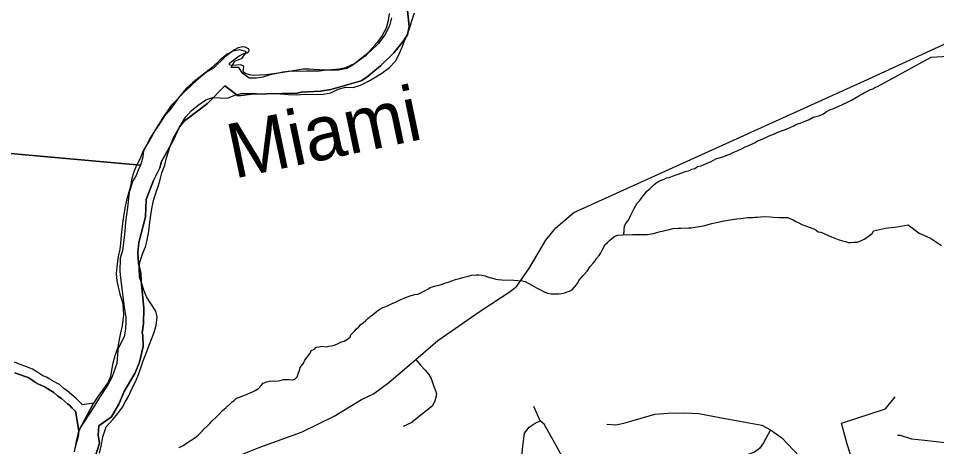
# Model space of a CAD drawing. Extents: x 0 to 34, y 0 to 22.
# Drawn here: x 3.323 to 4.119, y 17.214 to 17.586 of the extents above; entities that cross this region are included whole.
import ezdxf

# ---------------------------------------------------------------- set-up
doc = ezdxf.new("R2010")
doc.units = 0
for name, color, linetype in [('GM_X_Corporation', 7, 'Continuous'), ('GM_X_Major_River', 7, 'Continuous'), ('GM_X_Major_River_Text', 7, 'Continuous'), ('GM_X_Minor_River', 7, 'Continuous'), ('GM_X_Section', 7, 'Continuous'), ('GM_X_State_Route', 7, 'Continuous'), ('GM_X_Township_Road', 7, 'Continuous')]:
    doc.layers.add(name, color=color, linetype=linetype)

msp = doc.modelspace()

# ---------------------------------------------------------------- linework, layer by layer
at = {"layer": 'GM_X_Corporation'}
for points in [[(3.66027, 17.59244), (3.66153, 17.57843), (3.66011, 17.57121), (3.65674, 17.56596), (3.64838, 17.55552), (3.63677, 17.54452), (3.625, 17.53469), (3.62001, 17.53146), (3.59358, 17.52401), (3.58465, 17.52246), (3.56808, 17.52153), (3.56455, 17.52076), (3.52463, 17.5198), (3.51326, 17.51849), (3.50188, 17.52714), (3.48677, 17.51184), (3.46643, 17.49633), (3.46241, 17.49151), (3.45663, 17.47913), (3.44693, 17.46157), (3.44543, 17.45604), (3.4399, 17.44498), (3.43361, 17.42866), (3.43299, 17.41366), (3.42736, 17.39127), (3.42641, 17.38259), (3.42695, 17.37297), (3.42903, 17.36479), (3.42912, 17.35794), (3.43149, 17.33454), (3.4313, 17.321), (3.43021, 17.31263), (3.43079, 17.31107), (3.43091, 17.30105), (3.42783, 17.28746), (3.42393, 17.27842), (3.41461, 17.26212), (3.40987, 17.25112), (3.40354, 17.24031), (3.39245, 17.2323), (3.39208, 17.22427), (3.39303, 17.21741), (3.38732, 17.19913)], [(3.38732, 17.19913), (3.39303, 17.21741), (3.39208, 17.22427), (3.39245, 17.2323), (3.40354, 17.24031), (3.40987, 17.25112), (3.41461, 17.26212), (3.42393, 17.27842), (3.42783, 17.28746), (3.43091, 17.30105), (3.43079, 17.31107), (3.43021, 17.31263), (3.4313, 17.321), (3.43149, 17.33454), (3.42912, 17.35794), (3.42903, 17.36479), (3.42695, 17.37297), (3.42641, 17.38259), (3.42736, 17.39127), (3.43299, 17.41366), (3.43361, 17.42866), (3.4399, 17.44498), (3.44543, 17.45604), (3.44693, 17.46157), (3.45663, 17.47913), (3.46241, 17.49151), (3.46643, 17.49633), (3.48677, 17.51184), (3.50188, 17.52714), (3.51326, 17.51849), (3.52463, 17.5198), (3.56455, 17.52076), (3.56808, 17.52153), (3.58465, 17.52246), (3.59358, 17.52401), (3.62001, 17.53146), (3.625, 17.53469), (3.63677, 17.54452), (3.64838, 17.55552), (3.65674, 17.56596), (3.66011, 17.57121), (3.66153, 17.57843), (3.66027, 17.59244)]]:
    msp.add_lwpolyline(points, dxfattribs=at)
at = {"layer": 'GM_X_Major_River'}
msp.add_line((3.38806, 17.25203), (3.37508, 17.22818), dxfattribs=at)
for points in [[(3.64429, 17.58964), (3.64341, 17.58377), (3.64176, 17.57697), (3.63822, 17.57058), (3.63375, 17.5646), (3.62948, 17.55974), (3.62347, 17.55284), (3.61867, 17.54933), (3.61232, 17.54471), (3.60754, 17.54196), (3.60031, 17.54058), (3.5952, 17.5405), (3.59028, 17.5406), (3.58344, 17.53979), (3.57814, 17.53989), (3.57246, 17.53963), (3.56772, 17.53953), (3.56243, 17.53983), (3.55674, 17.53956), (3.55199, 17.5389), (3.54686, 17.53787), (3.54096, 17.53647), (3.53487, 17.53469), (3.52917, 17.53366), (3.52292, 17.53379), (3.51714, 17.53809), (3.51383, 17.5429), (3.50739, 17.54284), (3.51053, 17.54847), (3.51683, 17.55101), (3.52054, 17.55644), (3.51471, 17.55827), (3.50862, 17.55706), (3.50384, 17.5545), (3.49748, 17.54931), (3.49111, 17.54317), (3.48457, 17.53799), (3.47937, 17.53391), (3.47399, 17.52984), (3.46839, 17.52464), (3.46257, 17.51773), (3.45809, 17.51174), (3.45342, 17.50538), (3.44916, 17.50053), (3.44564, 17.49509), (3.44134, 17.48853), (3.43858, 17.48346), (3.43467, 17.47708), (3.43094, 17.4707), (3.42796, 17.46355), (3.42499, 17.45734), (3.42281, 17.45245), (3.42097, 17.44565), (3.4199, 17.43978), (3.41786, 17.43279), (3.41644, 17.42789), (3.41498, 17.42108), (3.41407, 17.41369), (3.413, 17.40782), (3.41252, 17.4029), (3.41204, 17.39759), (3.41132, 17.39039), (3.41065, 17.38546), (3.40939, 17.37922), (3.40826, 17.37032), (3.40758, 17.36445), (3.40821, 17.35817), (3.40923, 17.35283), (3.41081, 17.34653), (3.41294, 17.33965), (3.41377, 17.33393), (3.41386, 17.32862), (3.41338, 17.32388), (3.41271, 17.31895), (3.41126, 17.31291), (3.40999, 17.30591), (3.40911, 17.30022), (3.40651, 17.29306), (3.40467, 17.28664), (3.40342, 17.28078), (3.40255, 17.27529), (3.40056, 17.27039), (3.39606, 17.26365), (3.39236, 17.25859), (3.38806, 17.25203)], [(3.39306, 17.20882), (3.3945, 17.21487), (3.396, 17.22301), (3.39901, 17.23149), (3.40463, 17.23803), (3.4089, 17.24326), (3.41299, 17.24849), (3.41574, 17.25356), (3.41849, 17.25845), (3.42126, 17.26447), (3.42423, 17.27067), (3.42682, 17.27689), (3.42883, 17.28255), (3.43103, 17.28877), (3.43323, 17.29442), (3.43524, 17.30008), (3.43823, 17.30761), (3.44023, 17.3127), (3.44226, 17.31931), (3.44317, 17.32688), (3.44195, 17.33185), (3.43754, 17.33858), (3.43387, 17.34435), (3.43152, 17.34991), (3.4301, 17.35487), (3.42777, 17.36138), (3.42755, 17.36917), (3.42804, 17.37429), (3.43066, 17.38202), (3.43304, 17.38767), (3.43448, 17.39334), (3.43578, 17.4011), (3.4367, 17.40906), (3.43758, 17.41511), (3.43886, 17.42231), (3.44031, 17.42873), (3.44254, 17.43571), (3.44416, 17.44081), (3.44559, 17.44591), (3.44722, 17.45176), (3.44963, 17.45836), (3.45127, 17.46459), (3.4529, 17.47026), (3.45471, 17.47573), (3.4573, 17.48194), (3.46142, 17.48889), (3.46477, 17.49528), (3.4679, 17.50034), (3.47254, 17.50537), (3.4787, 17.51019), (3.48542, 17.5148), (3.49134, 17.51696), (3.49777, 17.51664), (3.5042, 17.51651), (3.5105, 17.51885), (3.51698, 17.52081), (3.52189, 17.52052), (3.52682, 17.52061), (3.53173, 17.52013), (3.53665, 17.52003), (3.54329, 17.52047), (3.5501, 17.52014), (3.5569, 17.51943), (3.56371, 17.51929), (3.57111, 17.51972), (3.58227, 17.51949), (3.58721, 17.51996), (3.59367, 17.52097), (3.60017, 17.52406), (3.60683, 17.52583), (3.61307, 17.5257), (3.61955, 17.52766), (3.62644, 17.53113), (3.63123, 17.53407), (3.63698, 17.53756), (3.64428, 17.54254), (3.6497, 17.54851), (3.65245, 17.55339), (3.65544, 17.56055), (3.65744, 17.56602), (3.66042, 17.5726), (3.66223, 17.57769), (3.66386, 17.58336), (3.66627, 17.59034)], [(3.37508, 17.22818), (3.3746, 17.22287), (3.37257, 17.21626), (3.37112, 17.21022)]]:
    msp.add_lwpolyline(points, dxfattribs=at)
at = {"layer": 'GM_X_Minor_River'}
msp.add_line((3.37508, 17.22818), (3.38806, 17.25203), dxfattribs=at)
for points in [[(4.06761, 17.52654), (4.11423, 17.55186), (4.19354, 17.55663)], [(3.84786, 17.39807), (3.84843, 17.40578), (3.84983, 17.40839), (3.85141, 17.41043), (3.8526, 17.4123), (3.85361, 17.41435), (3.85502, 17.41716), (3.85664, 17.42072), (3.85824, 17.42333), (3.85925, 17.42539), (3.86121, 17.42742), (3.86298, 17.42964), (3.86457, 17.43187), (3.86614, 17.43372), (3.86772, 17.43576), (3.87045, 17.43815), (3.87357, 17.4409), (3.87572, 17.44312), (3.87823, 17.44437), (3.88016, 17.44526), (3.88266, 17.44632), (3.88477, 17.44721), (3.88706, 17.44752), (3.88995, 17.44876), (3.89302, 17.44981), (3.89879, 17.4521), (3.9009, 17.4528), (3.90472, 17.45363), (3.90666, 17.45471), (3.90934, 17.45539), (3.91147, 17.45703), (3.91473, 17.45788), (3.918, 17.45911), (3.92012, 17.46019), (3.92339, 17.46161), (3.92763, 17.46376), (3.93243, 17.46532), (3.93588, 17.46654), (3.94088, 17.46829), (3.943, 17.46956), (3.94589, 17.47061), (3.95032, 17.47275), (3.95283, 17.47419), (3.9561, 17.47542), (3.96149, 17.47792), (3.96362, 17.47937), (3.96612, 17.48025), (3.96958, 17.48166), (3.97382, 17.48381), (3.97593, 17.48451), (3.97824, 17.48539), (3.98113, 17.48682), (3.98612, 17.48856), (3.98997, 17.48997), (3.99517, 17.49247), (3.99748, 17.49373), (4.00075, 17.49477), (4.00344, 17.49601), (4.00844, 17.49795), (4.01192, 17.49993), (4.01536, 17.50078), (4.01766, 17.50147), (4.02094, 17.50289), (4.02346, 17.50471), (4.02694, 17.50669), (4.02885, 17.5072), (4.03097, 17.50809), (4.03405, 17.50952), (4.03674, 17.51057), (4.04233, 17.51325), (4.04503, 17.51469), (4.04813, 17.51649), (4.0516, 17.51829), (4.05411, 17.51973), (4.05644, 17.52137), (4.05836, 17.52226), (4.06164, 17.52387), (4.06356, 17.52438), (4.06549, 17.52565), (4.06761, 17.52654)], [(3.64692, 17.33841), (3.64904, 17.3393), (3.65443, 17.34179), (3.65732, 17.34303), (3.65925, 17.34392), (3.66347, 17.3455), (3.66654, 17.34636), (3.66921, 17.34666), (3.67113, 17.34736), (3.6748, 17.34934), (3.67769, 17.35096), (3.67983, 17.35241), (3.68481, 17.35378), (3.68863, 17.35461), (3.69247, 17.35602), (3.69554, 17.35706), (3.69862, 17.35811), (3.70188, 17.35915), (3.70532, 17.35999), (3.7082, 17.36086), (3.71031, 17.36155), (3.7128, 17.36223), (3.71605, 17.36308), (3.71967, 17.36316), (3.72214, 17.36328), (3.72461, 17.36301), (3.72744, 17.36255), (3.73101, 17.36111), (3.73309, 17.36067), (3.73686, 17.3596), (3.73875, 17.35917), (3.74198, 17.35907), (3.75243, 17.35875), (3.75944, 17.35816), (3.76227, 17.3575), (3.76545, 17.3557), (3.76807, 17.35429), (3.772, 17.35189), (3.775, 17.35047), (3.77931, 17.34825), (3.78156, 17.34742), (3.78478, 17.34694), (3.78953, 17.3468), (3.79143, 17.34674), (3.79372, 17.34724), (3.79659, 17.34772), (3.7987, 17.34842), (3.80062, 17.34912), (3.80293, 17.35019), (3.8047, 17.35222), (3.80608, 17.35408), (3.80786, 17.35631), (3.80868, 17.35837), (3.81083, 17.36058), (3.81241, 17.36281), (3.81594, 17.3665), (3.81852, 17.37041), (3.82108, 17.37338), (3.82265, 17.37523), (3.82405, 17.37746), (3.8264, 17.38005), (3.82759, 17.38191), (3.8286, 17.38397), (3.82942, 17.38584), (3.83143, 17.38958), (3.83356, 17.39123), (3.83533, 17.39307), (3.83747, 17.3949), (3.8398, 17.39673), (3.84249, 17.39779), (3.84687, 17.39804), (3.84992, 17.39813), (3.85201, 17.39807), (3.85525, 17.39835), (3.86151, 17.39816), (3.86513, 17.39824), (3.86817, 17.39834), (3.87008, 17.39866), (3.87447, 17.39948), (3.87734, 17.40015), (3.88807, 17.40286), (3.89017, 17.40337), (3.89493, 17.4036), (3.89722, 17.40372), (3.90368, 17.40391), (3.90616, 17.40402), (3.91303, 17.40514), (3.91666, 17.40579), (3.92413, 17.40765), (3.92662, 17.40834), (3.93064, 17.40935), (3.93446, 17.41), (3.93656, 17.4105), (3.94152, 17.41111), (3.94344, 17.41162), (3.94572, 17.41174), (3.94897, 17.41221), (3.95107, 17.41253), (3.95507, 17.41298), (3.95697, 17.41292), (3.95944, 17.41304)], [(3.95944, 17.41304), (3.96135, 17.41317), (3.96363, 17.41329), (3.9663, 17.41359), (3.96916, 17.41369), (3.97447, 17.41353), (3.97713, 17.41326), (3.98225, 17.41291), (3.98453, 17.41284), (3.98776, 17.41293), (3.98985, 17.41287), (3.99173, 17.41205), (3.99454, 17.41083), (3.99679, 17.40943), (3.99942, 17.4084), (4.00203, 17.4068), (4.00523, 17.40576), (4.01238, 17.40307), (4.01444, 17.40206), (4.0163, 17.40067), (4.01819, 17.40024), (4.02007, 17.39961), (4.02439, 17.39777), (4.02777, 17.39634), (4.03078, 17.39511), (4.03359, 17.39388), (4.03736, 17.39263), (4.03982, 17.39217), (4.04245, 17.39133), (4.04454, 17.39127), (4.0474, 17.39156), (4.05007, 17.39167), (4.05237, 17.39236), (4.0543, 17.39344), (4.05623, 17.39433), (4.05854, 17.39559), (4.06087, 17.39723), (4.06321, 17.39944), (4.06434, 17.4015)], [(4.06434, 17.4015), (4.07447, 17.40361), (4.08474, 17.40475), (4.09425, 17.40647), (4.10376, 17.39943), (4.11365, 17.39505), (4.12316, 17.38858)], [(3.46222, 17.21356), (3.46569, 17.21536), (3.46841, 17.21736), (3.47576, 17.22208), (3.47868, 17.22446), (3.48201, 17.22777), (3.48397, 17.2298), (3.4865, 17.23201), (3.48866, 17.23441), (3.49082, 17.23662), (3.49395, 17.23976), (3.49667, 17.24214), (3.49963, 17.24566), (3.50255, 17.24804), (3.50802, 17.25319), (3.50995, 17.25427), (3.51191, 17.2563), (3.5146, 17.25736), (3.51671, 17.25824), (3.52113, 17.26001), (3.52364, 17.26107), (3.52575, 17.26196), (3.52806, 17.26303), (3.53097, 17.26484), (3.53332, 17.26742), (3.53489, 17.26927), (3.53817, 17.27069), (3.5418, 17.27153), (3.54502, 17.27125), (3.54826, 17.27153), (3.55075, 17.27202), (3.55266, 17.27253), (3.55571, 17.27263), (3.55761, 17.27257), (3.56026, 17.2723), (3.56256, 17.27299), (3.56451, 17.27483), (3.56576, 17.2784), (3.56658, 17.28047), (3.56722, 17.2831), (3.56999, 17.28682), (3.57101, 17.28926), (3.57416, 17.29315), (3.57555, 17.295), (3.57695, 17.29762), (3.57946, 17.29887), (3.58103, 17.30072), (3.5837, 17.30102), (3.5858, 17.30134), (3.58978, 17.30103), (3.59188, 17.30134), (3.59437, 17.30184), (3.59666, 17.30234), (3.59897, 17.30322), (3.60283, 17.30519), (3.60513, 17.30588), (3.60802, 17.3075), (3.61055, 17.30932), (3.61117, 17.3112), (3.61411, 17.31434), (3.61588, 17.31638), (3.61784, 17.31822), (3.61979, 17.32025), (3.62193, 17.32189), (3.62388, 17.32354), (3.62584, 17.32557), (3.62856, 17.32777), (3.63089, 17.3294), (3.63342, 17.33142), (3.63614, 17.33342), (3.63865, 17.33486), (3.64134, 17.33592), (3.64346, 17.33681), (3.64692, 17.33841)], [(3.38806, 17.25203), (3.3785, 17.25067), (3.37536, 17.25362), (3.37296, 17.25616), (3.37073, 17.25793), (3.36516, 17.26266), (3.36218, 17.26465), (3.35848, 17.26818), (3.35604, 17.2694), (3.35006, 17.273), (3.34726, 17.2746), (3.34406, 17.27584), (3.34219, 17.27703), (3.33884, 17.27922), (3.33491, 17.28162), (3.33078, 17.28327), (3.32288, 17.28616), (3.3195, 17.2876)], [(3.31983, 17.27845), (3.32782, 17.27552), (3.33119, 17.27418), (3.33441, 17.27221), (3.3377, 17.27007), (3.34029, 17.26841), (3.34368, 17.26709), (3.34587, 17.26584), (3.35205, 17.26212), (3.35366, 17.26132), (3.35698, 17.25815), (3.36016, 17.25603), (3.36546, 17.25153), (3.36733, 17.25004), (3.36951, 17.24774), (3.37242, 17.24501), (3.37508, 17.22818)], [(3.37508, 17.22818), (3.37242, 17.24501), (3.36951, 17.24774), (3.36733, 17.25004), (3.36546, 17.25153), (3.36016, 17.25603), (3.35698, 17.25815), (3.35366, 17.26132), (3.35205, 17.26212), (3.34587, 17.26584), (3.34368, 17.26709), (3.34029, 17.26841), (3.3377, 17.27007), (3.33441, 17.27221), (3.33119, 17.27418), (3.32782, 17.27552), (3.31983, 17.27845)], [(4.12923, 17.21735), (4.11839, 17.21849), (4.1085, 17.21963), (4.09747, 17.22097), (4.08758, 17.22401), (4.08488, 17.22397)]]:
    msp.add_lwpolyline(points, dxfattribs=at)
at = {"layer": 'GM_X_Section'}
for points in [[(3.64628, 17.58609), (3.64442, 17.57913), (3.64047, 17.57126), (3.635, 17.56361), (3.62823, 17.55732), (3.61456, 17.54644), (3.60652, 17.54263), (3.60082, 17.54162), (3.59095, 17.54069), (3.58357, 17.54104), (3.57487, 17.54161), (3.56975, 17.54153), (3.56101, 17.5402), (3.54847, 17.53801), (3.53727, 17.53674), (3.52646, 17.53602), (3.52325, 17.53647), (3.51968, 17.53769), (3.51837, 17.53866), (3.51764, 17.54), (3.51787, 17.5417), (3.5183, 17.54415), (3.51774, 17.54454), (3.51529, 17.54516), (3.50808, 17.54456), (3.50639, 17.54498), (3.50565, 17.54594), (3.50624, 17.54687), (3.51433, 17.55314), (3.51834, 17.55495), (3.52139, 17.55564), (3.52273, 17.55675), (3.52276, 17.55788), (3.52222, 17.55922), (3.51941, 17.56061), (3.51752, 17.56084), (3.51334, 17.55998), (3.51008, 17.55834), (3.50219, 17.55226), (3.49194, 17.54245), (3.4858, 17.53898), (3.47712, 17.53159), (3.46784, 17.52289), (3.45526, 17.51009), (3.44881, 17.50077), (3.43684, 17.48132), (3.4313, 17.47046), (3.4304, 17.46404), (3.42857, 17.45821), (3.19003, 17.47982)], [(3.19003, 17.47982), (3.42857, 17.45821), (3.42678, 17.45389), (3.42479, 17.44939), (3.42203, 17.44471), (3.41898, 17.43493), (3.41737, 17.42152), (3.41558, 17.40887), (3.41478, 17.3979), (3.41316, 17.38449), (3.41112, 17.37772), (3.41087, 17.36617), (3.41198, 17.35573), (3.41438, 17.33541), (3.41607, 17.32629), (3.416, 17.32288), (3.41567, 17.31626), (3.41458, 17.30946), (3.40944, 17.29954), (3.40902, 17.29765), (3.40802, 17.28631), (3.40378, 17.27428), (3.40043, 17.2681), (3.39318, 17.2569), (3.38808, 17.24886), (3.37534, 17.22887), (3.37308, 17.2204), (3.37115, 17.20984)]]:
    msp.add_lwpolyline(points, dxfattribs=at)
at = {"layer": 'GM_X_State_Route'}
msp.add_lwpolyline([(3.50832, 17.20451), (3.533, 17.2141), (3.56827, 17.22688), (3.59656, 17.24082), (3.62032, 17.25529), (3.6307, 17.2601), (3.6439, 17.26995), (3.66725, 17.29002), (3.68634, 17.30642), (3.71953, 17.32911), (3.7241, 17.33223), (3.74925, 17.34873), (3.75489, 17.35349), (3.7658, 17.3693), (3.78, 17.39335), (3.78886, 17.40408), (3.80444, 17.41728), (4.05642, 17.53128), (4.15316, 17.5758), (4.16297, 17.58031), (4.17429, 17.58179)], dxfattribs=at)
at = {"layer": 'GM_X_Township_Road'}
for points in [[(3.66725, 17.29002), (3.67147, 17.28487), (3.67551, 17.28053), (3.67864, 17.277), (3.68055, 17.27356), (3.68177, 17.27003), (3.68308, 17.2665), (3.68439, 17.26307), (3.6853, 17.26014), (3.68459, 17.25691), (3.68368, 17.25328), (3.68145, 17.24944), (3.6634, 17.23511), (3.65653, 17.23188)], [(4.01267, 17.18249), (4.03927, 17.1926), (4.04305, 17.1973), (4.04429, 17.20177), (4.04429, 17.20763), (4.04151, 17.21657), (4.03642, 17.23461), (4.07466, 17.24711), (4.08299, 17.25759)], [(3.97478, 17.22895), (3.96891, 17.21764), (3.96537, 17.2127), (3.96098, 17.20966), (3.95408, 17.20712), (3.91373, 17.19296), (3.90221, 17.18912), (3.89441, 17.18793), (3.8616, 17.18926), (3.81648, 17.1919), (3.8059, 17.19455), (3.80136, 17.1974), (3.79439, 17.20593), (3.7879, 17.21731), (3.77857, 17.23392), (3.77533, 17.23689), (3.76978, 17.24932)], [(3.83294, 17.23384), (3.84065, 17.23323), (3.84759, 17.23461), (3.85777, 17.23762), (3.87466, 17.24256), (3.88614, 17.24337), (3.90043, 17.24377), (3.91273, 17.24324), (3.93245, 17.2394), (3.96724, 17.23298), (3.97478, 17.22895), (3.98471, 17.22207), (4.00003, 17.20593)], [(3.75528, 17.18244), (3.7584, 17.19283), (3.75893, 17.20262), (3.76025, 17.21492), (3.76171, 17.22617), (3.76568, 17.23133), (3.77071, 17.23477), (3.77533, 17.23689)]]:
    msp.add_lwpolyline(points, dxfattribs=at)

# ---------------------------------------------------------------- texts
at = {"layer": 'GM_X_Major_River_Text'}
msp.add_text('Miami', height=0.047349, rotation=11.85843, dxfattribs=at).set_placement((3.50968, 17.44649))

doc.saveas('drawing.dxf')
